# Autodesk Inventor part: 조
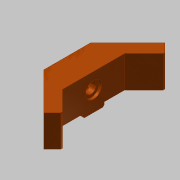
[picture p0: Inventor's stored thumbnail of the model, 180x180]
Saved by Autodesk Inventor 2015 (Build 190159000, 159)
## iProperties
Created: 2019-04
Part Number: 조
Material: 알루미늄 6061
Document SubType Name: Modeling
Designer: mduedu
Density: 1 g/cm^3
Appearance: 매끄러움 - 연한 주황색
Author: mduedu
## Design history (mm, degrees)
sketch "스케치1"
  geometry: L1 (45.962, 0)-(0, -45.962); L2 (0, -45.962)-(-45.962, 0); L3 (-45.962, 0)-(0, 45.962); L4 (0, 45.962)-(45.962, 0); L5 (45.962, 0)-(-45.962, 0); L6 (0, -45.962)-(0, 45.962); 1 further point
  constraints: 12 end point, 2 midpoint, 2 parallel, 2 perpendicular, 1 horizontal
  dimensions: "d0" = 65 distance of L1.end L2.end
extrude "돌출1" new body sketch "스케치1" distance "d2" = 27; taper "d3" = 0 deg
chamfer "모따기1" distance "d4" = 25; stored, may be unused: second distance "d5" = 2, angle "d6" = 45 deg
sketch "스케치2"
  geometry: L1 (-17.678, 28.284)-(-45.962, 0) reference; L2 (-17.678, 28.284)-(17.678, 28.284) reference; L3 (45.962, 0)-(17.678, 28.284) reference; L4 (-45.962, 0)-(0, -45.962) reference; L5 (0, -45.962)-(45.962, 0) reference; L6 (-23.536, 8.284)-(23.536, 8.284); L7 (-23.536, 8.284)-(-38.891, -7.071); L8 (38.891, -7.071)-(23.536, 8.284); 1 further point
  constraints: 6 end point, 3 parallel, 2 point on line
  dimensions: "d7" = 20 distance between parallel lines of L6 L2; "d8" = 10 distance between parallel lines of L1 L7; "d9" = 10 distance between parallel lines of L3 L8
extrude "돌출2" cut sketch "스케치2" stored distance "d10" = 27; taper "d11" = 0 deg
sketch "스케치3"
  geometry: L1 (63.64, -27)-(63.64, 0) reference; L2 (56.569, -27)-(63.64, -27) reference; L3 (-28.284, -27)-(-28.284, 0) reference; L4 (-28.284, -27)-(-21.213, -27) reference; L5 (63.64, -27)-(25.678, -27); L6 (25.678, -27)-(25.678, -24); L7 (25.678, -24)-(63.64, -24); L8 (63.64, -24)-(63.64, -27); L9 (-28.284, -27)-(9.678, -27); L10 (9.678, -27)-(9.678, -24); L11 (9.678, -24)-(-28.284, -24); L12 (-28.284, -24)-(-28.284, -27); L13 (41.213, 0)-(-5.858, 0) reference; L14 (17.678, -27)-(17.678, 0)
  constraints: 18 end point, 4 parallel, 2 horizontal, 2 perpendicular, 1 midpoint, 1 symmetric about line
  dimensions: "d12" = 3 distance between parallel lines of L5 L7; "d14" = 16 distance between parallel lines of L10 L6
extrude "돌출3" cut sketch "스케치3" stored distance "d15" = 27; taper "d16" = 0 deg
sketch "스케치4"
  geometry: L1 (31.536, -27)-(15.536, -27) reference; L2 (31.536, -24)-(47.071, -24) reference; 3 further points
  constraints: 1 midpoint, 1 vertical alignment
  dimensions: "d17" = 12 distance from line of L2 point (23.536, -12)
hole "구멍1" sketch "스케치4" at (23.536, -12) diameter "d18" = 8; stored, may be unused: countersink angle "d22" = 90 deg, drill point angle "d24" = 118 deg; dims "d19" = 6, "d20" = 12.5, "d21" = 2, "d23" = 14
node "작업 평면1"
sketch "스케치5"
  geometry: L1 (0, -15)-(0, 0); L2 (-50, -4)-(50, -4); L3 (50, -4)-(50, -1.75); L4 (-50, -1.75)-(-50, -4); L5 (12, -1.75)-(12, -2.75); L6 (12, -2.75)-(-12, -2.75); L7 (-12, -2.75)-(-12, -1.75); L8 (50, -1.75)-(12, -1.75); L9 (-12, -1.75)-(-50, -1.75); C1 r 4 at (0, 0) reference; 2 further points
  constraints: 18 end point, 4 parallel, 2 midpoint, 2 vertical, 2 vertical alignment, 1 collinear, 1 horizontal, 1 perpendicular, 1 tangent
  dimensions: "d26" = 2.5 diameter of L6 L2; "d28" = 4.5 diameter of L8 L2; "d29" = 24 distance of L5.end L6.end; "d30" = 100 distance between parallel lines of L3 L4
revolve "회전1" sketch "스케치5" stored, may be unused: angle "d31" = 90 deg
chamfer "모따기2" distance "d32" = 1; stored, may be unused: second distance "d33" = 2, angle "d34" = 45 deg
chamfer "모따기3" distance "d35" = 1; stored, may be unused: second distance "d36" = 2, angle "d37" = 45 deg
node "솔리드1"
other parameters: "d25" = -5
